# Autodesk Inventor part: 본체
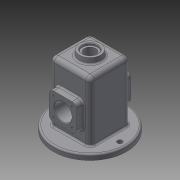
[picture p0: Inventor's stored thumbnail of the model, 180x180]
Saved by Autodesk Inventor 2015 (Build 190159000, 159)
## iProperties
Created: 2021-08
Part Number: 본체
Material: 일반
Document SubType Name: Modeling
Designer: 10401
Density: 1 g/cm^3
Appearance: 기본값
Author: 10401
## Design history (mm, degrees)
sketch "스케치1"
  geometry: L1 (-37, 37)-(37, 37); L2 (37, 37)-(37, -37); L3 (37, -37)-(-37, -37); L4 (-37, -37)-(-37, 37); L5 (-37, 37)-(37, -37); L6 (37, 37)-(-37, -37); 1 further point
  constraints: 12 end point, 2 midpoint, 2 parallel, 1 horizontal, 1 perpendicular
  dimensions: "d1" = 74 distance of L1.end L2.end; "d2" = 74 distance of L2.end L3.end
extrude "돌출1" new body sketch "스케치1" distance "d3" = 120; taper "d4" = 0 deg
fillet "모깎기1" dims "d5" = 8
fillet "모깎기2" dims "d6" = 8
feature "쉘1" dims "d7" = 5
sketch "스케치2"
  geometry: L1 (-29, 32)-(29, 32) reference; L2 (32, 29)-(32, -29) reference; L3 (29, -32)-(-29, -32) reference; L4 (-32, -29)-(-32, 29) reference; L5 (-29, -37)-(29, -37) reference; L6 (37, -29)-(37, 29) reference; L7 (29, 37)-(-29, 37) reference; L8 (-37, 29)-(-37, -29) reference; C1 r 67 at (0, 0); A1 r 3 centre (-29, 29) between (-29, 32) and (-32, 29) reference; A2 r 3 centre (29, 29) between (32, 29) and (29, 32) reference; A3 r 3 centre (29, -29) between (29, -32) and (32, -29) reference; A4 r 3 centre (-29, -29) between (-32, -29) and (-29, -32) reference; A5 r 8 centre (-29, -29) between (-37, -29) and (-29, -37) reference; A6 r 8 centre (29, -29) between (29, -37) and (37, -29) reference; A7 r 8 centre (29, 29) between (37, 29) and (29, 37) reference; A8 r 8 centre (-29, 29) between (-29, 37) and (-37, 29) reference; 1 further point
  constraints: 1 centre point, 1 coincident
  dimensions: "d68" = 134 diameter of C1
extrude "돌출2" join sketch "스케치2" distance "d8" = 10; taper "d9" = 0 deg
sketch "스케치3"
  geometry: C1 r 20 at (0, 0); 1 further point
  constraints: 1 centre point, 1 coincident
  dimensions: "d10" = 40 diameter of C1
extrude "돌출3" join sketch "스케치3" distance "d11" = 10; taper "d12" = 0 deg
sketch "스케치4"
  geometry: L1 (4, -82)-(54, -82); L2 (54, -82)-(54, -32); L3 (54, -32)-(4, -32); L4 (4, -32)-(4, -82); L5 (4, -82)-(54, -32); L6 (54, -82)-(4, -32); L7 (96, -112)-(-38, -112) reference; 3 further points
  constraints: 12 end point, 3 midpoint, 2 parallel, 1 horizontal, 1 perpendicular, 1 vertical alignment
  dimensions: "d13" = 50 distance of L2.end L3.end; "d14" = 50 distance of L1.end L2.end; "d15" = 55 distance from line of point (29, -57) L7
extrude "돌출4" join sketch "스케치4" distance "d16" = 13; taper "d18" = 0 deg; dims "d17" = 12, "d19" = 0
fillet "모깎기3" dims "d20" = 8
fillet "모깎기4" dims "d21" = 8
fillet "모깎기5" dims "d22" = 25
fillet "모깎기6" dims "d23" = 25
feature "면 기울기1" dims angle "d24" = 20 deg
feature "면 기울기2" dims angle "d25" = 20 deg
sketch "스케치5"
  geometry: C1 r 22.452 at (29, -57) reference; C2 r 16 at (29, -57); 1 further point
  constraints: 1 centre point, 1 coincident
  dimensions: "d26" = 32 diameter of C2
extrude "돌출5" cut sketch "스케치5" stored distance "d27" = 13; taper "d28" = 0 deg
sketch "스케치6"
  geometry: L1 (54, -74)-(54, -40) reference; L2 (46, -32)-(12, -32) reference; L3 (4, -40)-(4, -74) reference; L4 (12, -82)-(46, -82) reference; C1 r 16 at (29, -57) reference; A1 r 8 centre (46, -74) between (46, -82) and (54, -74) reference; A2 r 8 centre (46, -40) between (54, -40) and (46, -32) reference; A3 r 8 centre (12, -40) between (12, -32) and (4, -40) reference; A4 r 8 centre (12, -74) between (4, -74) and (12, -82) reference; 1 further point
hole "구멍1" sketch "스케치6" at (12, -40), (46, -40), (46, -74), (12, -74) diameter "d29" = 3.242; stored, may be unused: countersink angle "d33" = 90 deg, drill point angle "d35" = 118 deg; dims "d30" = 8, "d31" = 4, "d32" = 2, "d34" = 10
sketch "스케치7"
  geometry: A1 r 55 centre (0, 0) between (0, 55) and (-55, 0); 3 further points
  constraints: 4 point on circle, 1 centre point, 1 coincident
  dimensions: "d36" = 110 diameter of A1
hole "구멍2" sketch "스케치7" at (-55, 0), (55, 0) diameter "d37" = 9; stored, may be unused: countersink angle "d41" = 90 deg, drill point angle "d43" = 118 deg; dims "d38" = 8, "d39" = 4, "d40" = 2, "d42" = 10
fillet "모깎기7" dims "d44" = 3
sketch "스케치8"
  geometry: 1 further point
hole "구멍3" sketch "스케치8" at (0, 0) diameter "d45" = 21; stored, may be unused: countersink angle "d49" = 90 deg, drill point angle "d51" = 118 deg; dims "d46" = 8, "d47" = 28, "d48" = 4, "d50" = 10
fillet "모깎기8" dims "d52" = 3
fillet "모깎기9" dims "d53" = 3
chamfer "모따기1" distance "d54" = 1; stored, may be unused: second distance "d55" = 2, angle "d56" = 45 deg
sketch "스케치9"
  geometry: L1 (49, 18)-(9, 18) reference; L2 (-8, 0)-(-8, -99) reference; 2 further points
  constraints: 1 other
  dimensions: "d57" = 28 distance from line of point (29, -10) L1; "d58" = 37 distance from line of L2 point (29, -10)
feature "엠보싱1" sketch "스케치9" dims "d1" = 74, "d2" = 74, "d59" = 0.5, "d60" = 0
sketch "스케치10"
  geometry: L1 (42, -8)-(42, -42) reference; L2 (0, 0)-(34, 0) reference; L3 (-8, -42)-(-8, -8) reference; L4 (34, -50)-(0, -50) reference; C1 r 17 at (17, -25) reference; A1 r 8 centre (34, -42) between (34, -50) and (42, -42) reference; A2 r 8 centre (34, -8) between (42, -8) and (34, 0) reference; A3 r 8 centre (0, -8) between (0, 0) and (-8, -8) reference; A4 r 8 centre (0, -42) between (-8, -42) and (0, -50) reference; 1 further point
hole "구멍4" sketch "스케치10" at (0, -8), (34, -8), (34, -42), (0, -42) diameter "d61" = 3.242; stored, may be unused: countersink angle "d65" = 90 deg, drill point angle "d67" = 118 deg; dims "d62" = 8, "d63" = 4, "d64" = 2, "d66" = 10
feature "면 기울기3" dims angle "d69" = 6 deg
fillet "모깎기10" dims "d70" = 3
node "솔리드1"
mirror "대칭1"
node "투영된 루프1"
node "투영된 루프2"
node "투영된 루프3"
